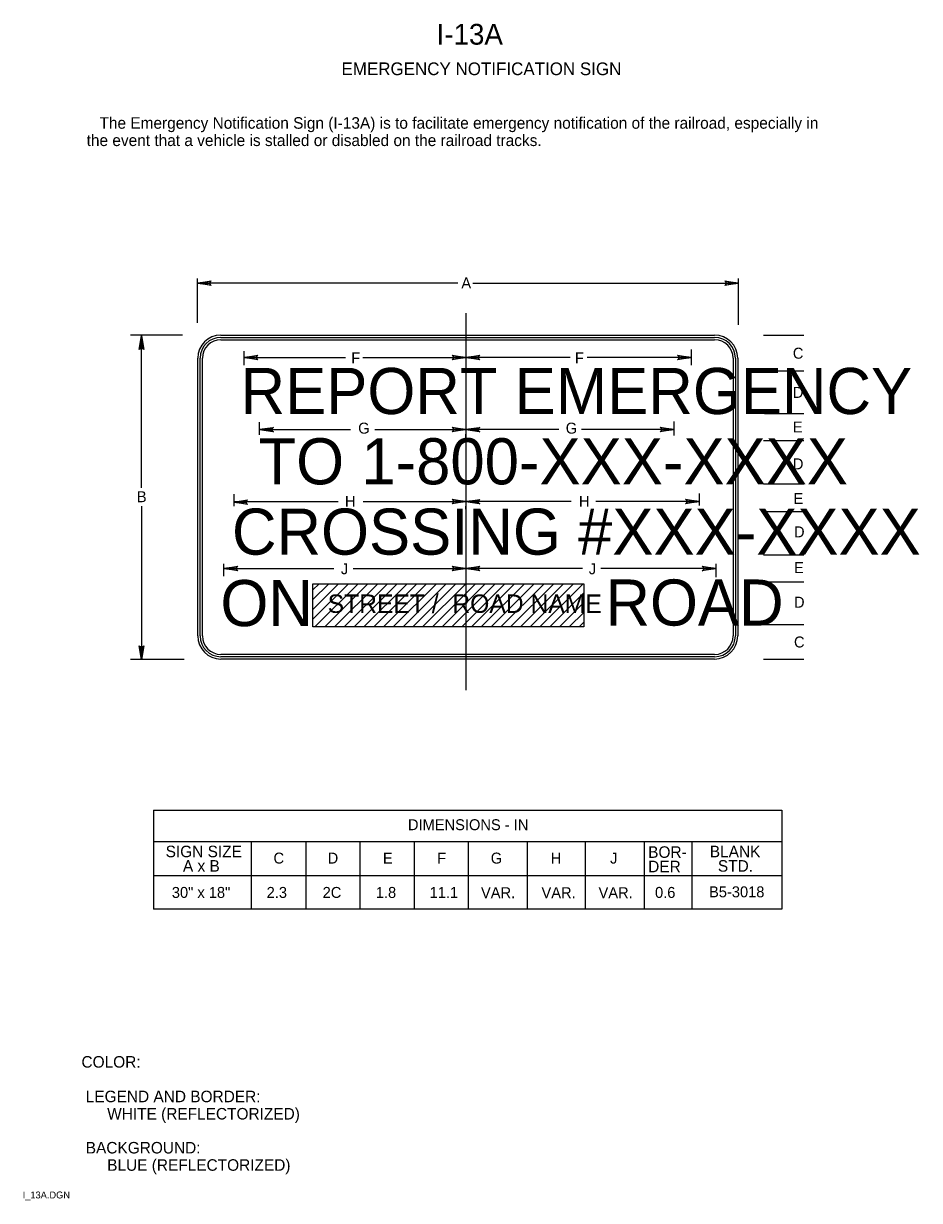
# Model space of a CAD drawing. Extents: x 0.013 to 0.207, y 0.004 to 0.259.
import ezdxf

# ---------------------------------------------------------------- set-up
doc = ezdxf.new("R2010")
doc.units = 0
for name, color, linetype in [('1', 7, 'Continuous'), ('2', 7, 'Continuous'), ('3', 7, 'Continuous')]:
    doc.layers.add(name, color=color, linetype=linetype)

# ---------------------------------------------------------------- blocks, each defined once
blk = doc.blocks.new('RARROW')
at = {"layer": '3'}
for p, q in [((-2.156, 0.285), (-2.2665, 0.384625)), ((-2.2665, 0.384625), (0, 0)), ((0, 0), (-2.2665, -0.379125)), ((-2.156, 0.285), (-2.075625, 0.12075)), ((0, 0), (-2.156, 0.285)), ((-2.14975, -0.2705), (0, 0)), ((-2.075625, 0.12075), (0, 0)), ((0, 0), (-2.074, -0.108)), ((-2.2665, -0.379125), (-2.14975, -0.2705)), ((-2.074, -0.108), (-2.14975, -0.2705))]:
    blk.add_line(p, q, dxfattribs=at)

msp = doc.modelspace()

# ---------------------------------------------------------------- linework, layer by layer
at = {"layer": '1'}
for p, q in [((0.10862, 0.19637), (0.10862, 0.11463)), ((0.17313, 0.19163), (0.18188, 0.19163)), ((0.17313, 0.18388), (0.18188, 0.18388)), ((0.17338, 0.17463), (0.18188, 0.17463)), ((0.17313, 0.16875), (0.18188, 0.16875)), ((0.17313, 0.15938), (0.18188, 0.15938)), ((0.17313, 0.15338), (0.18188, 0.15338)), ((0.17313, 0.144), (0.18188, 0.144)), ((0.17313, 0.13812), (0.18188, 0.13812)), ((0.17313, 0.12887), (0.18188, 0.12887)), ((0.17313, 0.12137), (0.18188, 0.12137))]:
    msp.add_line(p, q, dxfattribs=at)
at = {"layer": '3'}
for p, q in [((0.05038, 0.19425), (0.05038, 0.20388)), ((0.10687, 0.20287), (0.05038, 0.20287)), ((0.11013, 0.20287), (0.16775, 0.20287)), ((0.16775, 0.19387), (0.16775, 0.20388)), ((0.04713, 0.19163), (0.03588, 0.19163)), ((0.03825, 0.1585), (0.03825, 0.19163)), ((0.05547, 0.19162), (0.16255, 0.19162)), ((0.05547, 0.19112), (0.16255, 0.19112)), ((0.05547, 0.19062), (0.16255, 0.19062)), ((0.10862, 0.19013), (0.10862, 0.18575)), ((0.05047, 0.12637), (0.05047, 0.18662)), ((0.05097, 0.12637), (0.05097, 0.18662)), ((0.05147, 0.12637), (0.05147, 0.18662)), ((0.0605, 0.18513), (0.0605, 0.18813)), ((0.0605, 0.18675), (0.0825, 0.18675)), ((0.08625, 0.18675), (0.10862, 0.18675)), ((0.13125, 0.18675), (0.10862, 0.18675)), ((0.1575, 0.18675), (0.13493, 0.18675)), ((0.1575, 0.18513), (0.1575, 0.1885)), ((0.16655, 0.18662), (0.16655, 0.12637)), ((0.16705, 0.18662), (0.16705, 0.12637)), ((0.16755, 0.18662), (0.16755, 0.12637)), ((0.06388, 0.17), (0.06388, 0.17275)), ((0.06388, 0.17112), (0.08358, 0.17112)), ((0.08885, 0.17112), (0.10862, 0.17112)), ((0.12874, 0.17112), (0.10862, 0.17112)), ((0.15375, 0.17112), (0.13367, 0.17112)), ((0.15375, 0.16987), (0.15375, 0.17288)), ((0.10862, 0.16937), (0.10862, 0.17012)), ((0.05838, 0.1545), (0.05838, 0.15713)), ((0.15925, 0.15463), (0.15925, 0.15725)), ((0.03825, 0.1545), (0.03825, 0.12137)), ((0.05838, 0.1555), (0.08091, 0.1555)), ((0.08632, 0.1555), (0.10862, 0.1555)), ((0.13141, 0.1555), (0.10862, 0.1555)), ((0.10862, 0.15388), (0.10862, 0.1545)), ((0.15925, 0.1555), (0.13675, 0.1555)), ((0.10862, 0.14388), (0.10862, 0.14)), ((0.05613, 0.13937), (0.05613, 0.142)), ((0.05613, 0.141), (0.08, 0.141)), ((0.08417, 0.141), (0.10862, 0.141)), ((0.13387, 0.141), (0.10862, 0.141)), ((0.16287, 0.141), (0.1379, 0.141)), ((0.16287, 0.13912), (0.16287, 0.142)), ((0.07545, 0.13639), (0.07676, 0.13769)), ((0.07545, 0.13426), (0.07888, 0.13769)), ((0.07545, 0.13214), (0.081, 0.13769)), ((0.07545, 0.13002), (0.08312, 0.13769)), ((0.07588, 0.12833), (0.08524, 0.13769)), ((0.078, 0.12833), (0.08736, 0.13769)), ((0.08012, 0.12833), (0.08949, 0.13769)), ((0.08224, 0.12833), (0.09161, 0.13769)), ((0.08437, 0.12833), (0.09373, 0.13769)), ((0.08649, 0.12833), (0.09585, 0.13769)), ((0.08861, 0.12833), (0.09797, 0.13769)), ((0.09073, 0.12833), (0.10009, 0.13769)), ((0.09285, 0.12833), (0.10221, 0.13769)), ((0.09497, 0.12833), (0.10433, 0.13769)), ((0.09709, 0.12833), (0.10646, 0.13769)), ((0.09921, 0.12833), (0.10858, 0.13769)), ((0.10134, 0.12833), (0.1107, 0.13769)), ((0.10346, 0.12833), (0.11282, 0.13769)), ((0.10558, 0.12833), (0.11494, 0.13769)), ((0.1077, 0.12833), (0.11706, 0.13769)), ((0.10982, 0.12833), (0.11918, 0.13769)), ((0.11194, 0.12833), (0.12131, 0.13769)), ((0.11406, 0.12833), (0.12343, 0.13769)), ((0.11619, 0.12833), (0.12555, 0.13769)), ((0.11831, 0.12833), (0.12767, 0.13769)), ((0.12043, 0.12833), (0.12979, 0.13769)), ((0.12255, 0.12833), (0.13191, 0.13769)), ((0.12467, 0.12833), (0.13403, 0.13769)), ((0.12679, 0.12833), (0.1342, 0.13574)), ((0.12891, 0.12833), (0.1342, 0.13361)), ((0.13103, 0.12833), (0.1342, 0.13149)), ((0.13316, 0.12833), (0.1342, 0.12937)), ((0.0475, 0.12125), (0.03588, 0.12125)), ((0.16255, 0.12237), (0.05547, 0.12237)), ((0.16255, 0.12187), (0.05547, 0.12187)), ((0.16255, 0.12137), (0.05547, 0.12137)), ((0.04088, 0.08862), (0.17713, 0.08862)), ((0.04088, 0.08862), (0.04088, 0.06713)), ((0.17713, 0.08862), (0.17713, 0.06713)), ((0.17713, 0.08175), (0.04088, 0.08175)), ((0.06208, 0.08175), (0.06208, 0.06712)), ((0.07387, 0.08175), (0.07387, 0.06713)), ((0.08563, 0.08175), (0.08563, 0.06713)), ((0.09738, 0.08175), (0.09738, 0.06713)), ((0.10912, 0.08175), (0.10912, 0.06713)), ((0.12187, 0.08175), (0.12187, 0.06713)), ((0.1345, 0.08175), (0.1345, 0.06713)), ((0.14725, 0.08175), (0.14725, 0.06713)), ((0.15759, 0.08175), (0.15759, 0.06712)), ((0.17713, 0.07437), (0.04088, 0.07437)), ((0.17713, 0.06713), (0.04088, 0.06713))]:
    msp.add_line(p, q, dxfattribs=at)
msp.add_lwpolyline([(0.07545, 0.13769), (0.1342, 0.13769), (0.1342, 0.12833), (0.07545, 0.12833)], close=True, dxfattribs=at)
for centre, radius, start, end in [((0.05547, 0.18662), 0.005, 90, 180), ((0.16255, 0.18662), 0.005, 0, 90), ((0.05547, 0.18662), 0.0045, 90, 180), ((0.05547, 0.18662), 0.004, 90, 180), ((0.16255, 0.18662), 0.0045, 0, 90), ((0.16255, 0.18662), 0.004, 0, 90), ((0.05547, 0.12637), 0.005, 180, 270), ((0.05547, 0.12637), 0.0045, 180, 270), ((0.05547, 0.12637), 0.004, 180, 270), ((0.16255, 0.12637), 0.005, 270, 0), ((0.16255, 0.12637), 0.0045, 270, 0), ((0.16255, 0.12637), 0.004, 270, 0)]:
    msp.add_arc(centre, radius, start, end, dxfattribs=at)

# ---------------------------------------------------------------- block references
at = {"layer": '3', "xscale": 0.0013236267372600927, "yscale": 0.001309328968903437}
for p, rotation in [((0.05038, 0.20287), 180), ((0.03825, 0.1915), 90), ((0.0605, 0.18675), 180), ((0.10862, 0.18675), 180), ((0.06388, 0.17112), 180), ((0.10862, 0.17112), 180), ((0.05825, 0.15538), 180), ((0.10862, 0.1555), 180), ((0.05613, 0.141), 180), ((0.10862, 0.141), 180), ((0.03825, 0.12125), -90)]:
    msp.add_blockref('RARROW', p, dxfattribs=dict(at, rotation=rotation))
for p in [(0.16775, 0.20287), (0.10862, 0.18675), (0.1575, 0.18675), (0.10862, 0.17112), (0.15375, 0.17112), (0.10862, 0.1555), (0.15925, 0.1555), (0.10862, 0.141), (0.16287, 0.141)]:
    msp.add_blockref('RARROW', p, dxfattribs=at)

# ---------------------------------------------------------------- texts
at = {"layer": '1'}
for s, height, p in [('I-13A', 0.0045, (0.10225, 0.25462)), ('EMERGENCY NOTIFICATION SIGN', 0.0027503, (0.08163, 0.248)), ('COLOR:', 0.0025, (0.02525, 0.03275)), (' LEGEND AND BORDER:', 0.0024998, (0.02525, 0.02525)), ('      WHITE (REFLECTORIZED)', 0.0024998, (0.02525, 0.0215)), (' BACKGROUND:', 0.0024998, (0.02525, 0.01413)), ('      BLUE (REFLECTORIZED)', 0.0024998, (0.02525, 0.01038)), ('I_13A.DGN', 0.0015, (0.0125, 0.00438))]:
    msp.add_text(s, height=height, dxfattribs=at).set_placement(p)
at = {"layer": '2'}
for s, height, p in [('   The Emergency Notification Sign (I-13A) is to facilitate emergency notification of the railroad, especially in', 0.00249975, (0.02637, 0.23638)), ('the event that a vehicle is stalled or disabled on the railroad tracks.', 0.0024998, (0.02637, 0.23262)), ('C', 0.00238, (0.1795, 0.1865)), ('REPORT EMERGENCY', 0.0099997, (0.05975, 0.1745)), ('D', 0.00238, (0.1795, 0.178)), ('TO 1-800-XXX-XXXX', 0.0099997, (0.06363, 0.15925)), ('D', 0.00238, (0.1795, 0.1625)), ('B', 0.00238, (0.03725, 0.15538)), ('CROSSING #XXX-XXXX', 0.0099997, (0.05788, 0.144)), ('D', 0.00238, (0.17975, 0.14775)), ('ON', 0.01, (0.05538, 0.1285)), ('ROAD', 0.01, (0.13887, 0.12862)), ('STREET /  ROAD NAME', 0.0039997, (0.07863, 0.13137)), ('D', 0.00238, (0.17975, 0.1325)), ('C', 0.00238, (0.17975, 0.12387))]:
    msp.add_text(s, height=height, dxfattribs=at).set_placement(p)
at = {"layer": '3'}
for s, height, p in [('A', 0.00238, (0.10762, 0.20175)), ('F', 0.00238, (0.08375, 0.1855)), ('F', 0.00238, (0.13225, 0.1855)), ('G', 0.00238, (0.08525, 0.17025)), ('G', 0.00238, (0.13025, 0.17025)), ('E', 0.00238, (0.1795, 0.1705)), ('H', 0.00238, (0.08238, 0.15438)), ('H', 0.00238, (0.13312, 0.15438)), ('E', 0.00238, (0.17963, 0.155)), ('J', 0.00238, (0.0815, 0.13975)), ('J', 0.00238, (0.13525, 0.13975)), ('E', 0.00238, (0.17975, 0.14)), ('DIMENSIONS - IN', 0.0023752, (0.09604, 0.08425)), ('SIGN SIZE', 0.0025, (0.0435, 0.07838)), ('C', 0.00238, (0.06688, 0.077)), ('D', 0.00238, (0.07863, 0.077)), ('E', 0.00238, (0.09062, 0.077)), ('F', 0.00238, (0.10238, 0.077)), ('G', 0.00238, (0.114, 0.077)), ('H', 0.00238, (0.127, 0.077)), ('J', 0.00238, (0.13987, 0.077)), ('BOR-', 0.0025, (0.14813, 0.07825)), ('BLANK', 0.0025, (0.1615, 0.07838)), ('A x B', 0.0025, (0.04725, 0.07525)), ('DER', 0.0025, (0.14813, 0.07512)), ('STD.', 0.0025, (0.16325, 0.07525)), ('30" x 18"', 0.002375, (0.04484, 0.06956)), ('2.3', 0.002375, (0.0654, 0.06956)), ('2C', 0.002375, (0.07754, 0.06956)), ('1.8', 0.002375, (0.08907, 0.06956)), ('11.1', 0.002375, (0.10074, 0.06956)), ('VAR.', 0.002375, (0.11188, 0.0695)), ('VAR.', 0.002375, (0.125, 0.0695)), ('VAR.', 0.002375, (0.13737, 0.0695)), ('0.6', 0.002375, (0.14962, 0.06956)), ('B5-3018', 0.002375, (0.16133, 0.06969))]:
    msp.add_text(s, height=height, dxfattribs=at).set_placement(p)

doc.saveas('drawing.dxf')
